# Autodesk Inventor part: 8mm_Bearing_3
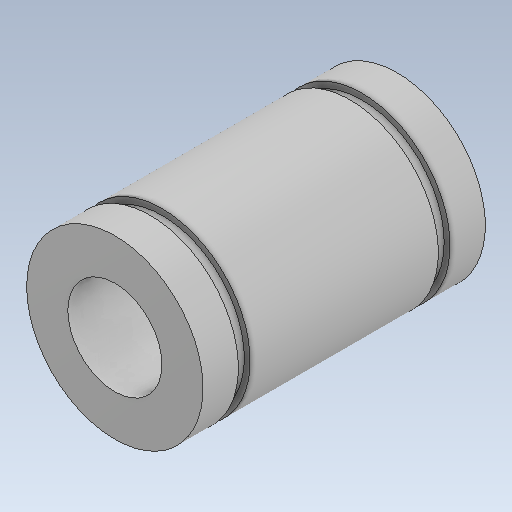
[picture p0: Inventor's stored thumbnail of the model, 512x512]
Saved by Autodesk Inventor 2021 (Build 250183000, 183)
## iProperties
Created: 2026-10
Part Number: 8mm_Bearing_3
Material: Steel
Document SubType Name: Modeling
Designer: hp
Density: 7.85 g/cm^3
Appearance: Default
Author: hp
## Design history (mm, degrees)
feature "Body1"
body "Solid1"
